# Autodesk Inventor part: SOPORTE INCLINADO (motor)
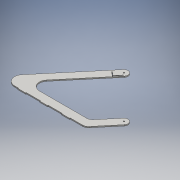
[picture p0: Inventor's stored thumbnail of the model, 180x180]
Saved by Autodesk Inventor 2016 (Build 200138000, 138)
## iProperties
Created: 2016-06
Part Number: SOPORTE INCLINADO (motor)
Material: Genérico
Document SubType Name: Modeling
Designer: adm
Density: 1 g/cm^3
Appearance: Valor por defecto
Author: adm
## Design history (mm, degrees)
sketch "Boceto1"
  geometry: L1 (75.83, -250.705)-(156.742, -154.277); L2 (57.177, -210.705)-(126.1, -128.566); L3 (34.196, -221.421)-(-203.95, -221.421); L4 (-54.102, 59.39)-(-234.592, -155.71); L5 (-86.032, 83.566)-(-320.372, -195.71); L6 (-269.73, -261.421)-(-269.73, -264.421); L7 (-229.73, -261.421)-(-229.73, -264.421); L8 (-159.73, -261.421)-(-159.73, -264.421); L9 (-119.73, -261.421)-(-119.73, -264.421); L10 (-49.73, -261.421)-(-49.73, -264.421); L11 (-9.73, -261.421)-(-9.73, -264.421); L12 (-49.73, -264.421)-(-9.73, -264.421); L13 (-269.73, -264.421)-(-229.73, -264.421); L14 (-159.73, -264.421)-(-119.73, -264.421); L15 (52.848, -261.421)-(-9.73, -261.421); L16 (-49.73, -261.421)-(-119.73, -261.421); L17 (-159.73, -261.421)-(-229.73, -261.421); L18 (-269.73, -261.421)-(-289.73, -261.421); C1 r 3.25 at (141.421, -141.421); C2 r 3.25 at (-70.711, 70.711); A1 r 30 centre (52.848, -231.421) between (52.848, -261.421) and (75.83, -250.705); A2 r 20 centre (141.421, -141.421) between (156.742, -154.277) and (126.1, -128.566); A3 r 30 centre (34.196, -191.421) between (34.196, -221.421) and (57.177, -210.705); A4 r 20.1 centre (-70.711, 70.711) between (-56.678, 56.32) and (-87.319, 82.032); A5 r 40 centre (-203.95, -181.421) between (-234.592, -155.71) and (-203.95, -221.421); A6 r 40 centre (-289.73, -221.421) between (-320.372, -195.71) and (-289.73, -261.421); 3 further points
  constraints: 36 end point, 15 tangent, 13 point on circle, 8 centre point, 2 coincident, 2 point on line
  dimensions: "d3" = 40 radius of A6; "d5" = 40 radius of A5; "d6" = 30 radius of A3; "d7" = 30 radius of A1; "d20" = 6.5 diameter of C2; "d21" = 6.5 diameter of C1
extrude "Extrusión1" new body sketch "Boceto1" distance "d18" = 6; taper "d19" = 0 deg
sketch "Boceto3"
  geometry: L1 (104.083, 46.497)-(88.762, 33.641); L2 (106.14, 44.045)-(90.819, 31.19); L3 (104.083, 46.497)-(106.14, 44.045); L4 (88.762, 33.641)-(90.819, 31.19); L5 (62.809, 59.903)-(88.521, 29.261); L6 (60.358, 57.846)-(86.069, 27.204); L7 (62.809, 59.903)-(60.358, 57.846); L8 (98.479, 37.618)-(90.819, 31.19); L9 (88.521, 29.261)-(86.069, 27.204); 3 further points
  constraints: 18 end point, 4 parallel, 1 coincident, 1 midpoint
  dimensions: "d50" = 3.2 distance between parallel lines of L1 L2; "d51" = 3.2 distance between parallel lines of L5 L6
extrude "Extrusión3" cut sketch "Boceto3" distance "d52" = 10; taper "d53" = 0 deg
node "Sólido1"
other parameters: "d4" = 50 deg, "d11" = 3, "d23" = 3, "d33" = 3, "d34" = 2
